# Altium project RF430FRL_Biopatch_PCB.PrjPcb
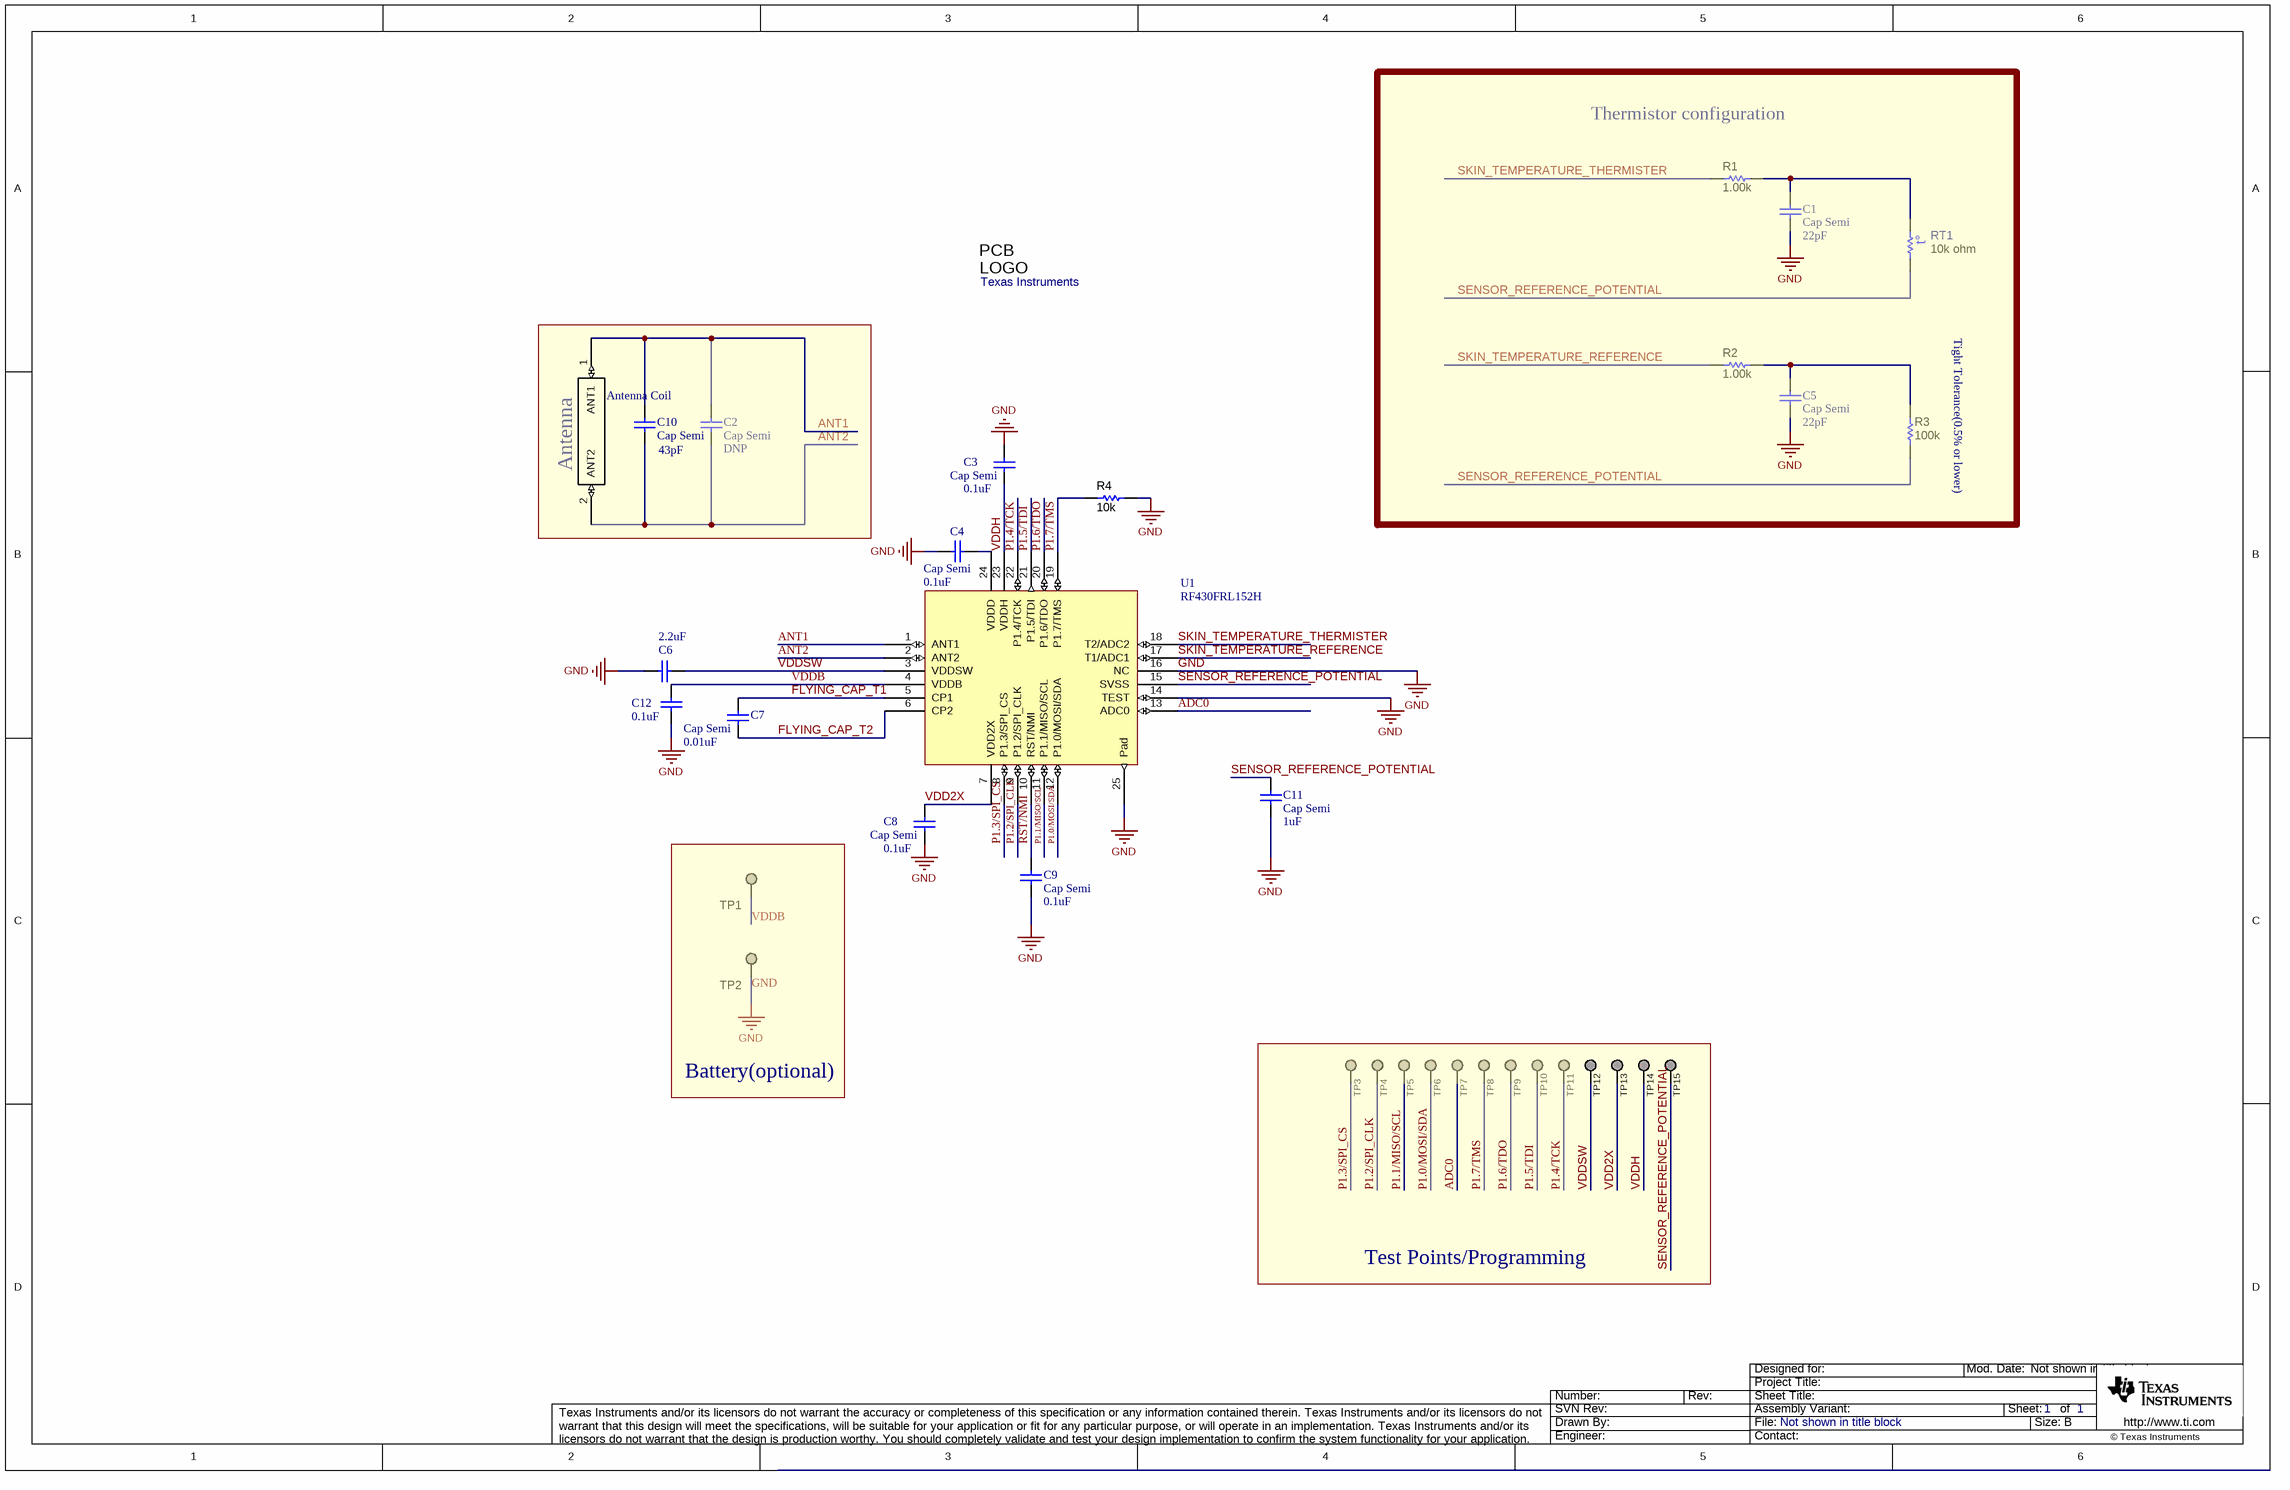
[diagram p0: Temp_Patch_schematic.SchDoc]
1 sheet, 35 parts. Net scope: global (net labels, ports and power ports of the same name join across sheets).
Board file: RF430FRL_Biopatch_Layout.PcbDoc

## Sheet Temp_Patch_schematic.SchDoc
size 431 x 279 mm; Date: Not shown in title block; ApprovedBy: Not shown in title block; CheckedBy: Not shown in title block; Author: Not shown in title block; CompanyName: Not shown in title block; Engineer: Not shown in title block; Organization: Not shown in title block; Address1: Not shown in title block; Address2: Not shown in title block; Address3: Not shown in title block; Address4: Not shown in title block; DocumentNumber: 1; Revision: Use project parameter SCH_Rev; SheetNumber: 1; SheetTotal: 1; PageSetup: Record=PageOptions|CenterHorizontal=True|CenterVertical=True|PrintScale=0.64|XCorrection=1.00|YCorrection=1.00|PrintKind=0|BorderSize=5000000|LeftOffset=0|BottomOffset=0|Orientation=2|PaperLength=1000|PaperWidth=1000|Scale=100|PaperSource=15|PrintQuality=600|MediaType=1|DitherType=10|PaperKind=Letter|PrintScaleMode=1

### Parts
Antenna_Coil  Antenna Coil  [PCBComponent_1]
C1  Cap Semi  value 22pF  [0402]
C2  Cap Semi  value DNP  [0402]
C3  Cap Semi  value 0.1uF  [0402]
C4  Cap Semi  value 0.1uF  [0402]
C5  Cap Semi  value 22pF  [0402]
C6  value 2.2uF  [0402]  (hidden comment: Cap Semi)
C7  Cap Semi  value 0.01uF  [0402]
C8  Cap Semi  value 0.1uF  [0402]
C9  Cap Semi  value 0.1uF  [0402]
C10  Cap Semi  value 43pF  [0402]
C11  Cap Semi  value 1uF  [0402]
C12  value 0.1uF  [0402]  (hidden comment: Cap Semi)
Logo?  Texas Instruments  [TI_Symbol_Overlay_Small]  (no BOM)
R1  ValueDisplayed: 1.00k  [0402]  (hidden comment: CRCW04021K00FKED)
R2  ValueDisplayed: 1.00k  [0402]  (hidden comment: CRCW04021K00FKED)
R3  ValueDisplayed: 100k  [0402]  (hidden comment: CRCW0402100KJNED)
R4  ValueDisplayed: 10k  [0402]  (hidden comment: CRCW040210K0JNED)
RT1  value 10k ohm  [0603]  (hidden comment: 103AT-2)
TP1  TESTPOINT  [TESTPOINT]  (value not drawn)  (no BOM)
TP2  TESTPOINT  [TESTPOINT]  (value not drawn)  (no BOM)
TP3  TESTPOINT  [TESTPOINT]  (value not drawn)  (no BOM)
TP4  TESTPOINT  [TESTPOINT]  (value not drawn)  (no BOM)
TP5  TESTPOINT  [TESTPOINT]  (value not drawn)  (no BOM)
TP6  TESTPOINT  [TESTPOINT]  (value not drawn)  (no BOM)
TP7  TESTPOINT  [TESTPOINT]  (value not drawn)  (no BOM)
TP8  TESTPOINT  [TESTPOINT]  (value not drawn)  (no BOM)
TP9  TESTPOINT  [TESTPOINT]  (value not drawn)  (no BOM)
TP10  TESTPOINT  [TESTPOINT]  (value not drawn)  (no BOM)
TP11  TESTPOINT  [TESTPOINT]  (value not drawn)  (no BOM)
TP12  TESTPOINT  [TESTPOINT]  (value not drawn)  (no BOM)
TP13  TESTPOINT  [TESTPOINT]  (value not drawn)  (no BOM)
TP14  TESTPOINT  [TESTPOINT]  (value not drawn)  (no BOM)
TP15  TESTPOINT  [TESTPOINT]  (value not drawn)  (no BOM)
U1  RF430FRL152H  [RGE24_2P7X2P7]

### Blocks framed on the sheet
Thermistor configuration: C1 C5 R1-R3 RT1
Antenna: Antenna_Coil C2 C10
Battery(optional): TP1 TP2
Test Points/Programming: TP3-TP15

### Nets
GND: C1.1 C3.2 C4.2 C5.1 C6.2 C8.1 C9.1 C11.1 C12.1 R4.2 TP2.1 U1.14(TEST) U1.16(NC) U1.25(Pad)
ADC0: TP7.1 U1.13(ADC0)
ANT1: Antenna_Coil.1(ANT1) C2.2 C10.2 U1.1(ANT1)
ANT2: Antenna_Coil.2(ANT2) C2.1 C10.1 U1.2(ANT2)
FLYING_CAP_T1: C7.2 U1.5(CP1)
FLYING_CAP_T2: C7.1 U1.6(CP2)
P1.0/MOSI/SDA: TP6.1 U1.12(P1.0/MOSI/SDA)
P1.1/MISO/SCL: TP5.1 U1.11(P1.1/MISO/SCL)
P1.2/SPI_CLK: TP4.1 U1.9(P1.2/SPI_CLK)
P1.3/SPI_CS: TP3.1 U1.8(P1.3/SPI_CS)
P1.4/TCK: TP11.1 U1.22(P1.4/TCK)
P1.5/TDI: TP10.1 U1.21(P1.5/TDI)
P1.6/TDO: TP9.1 U1.20(P1.6/TDO)
P1.7/TMS: R4.1 TP8.1 U1.19(P1.7/TMS)
RST/NMI: C9.2 U1.10(RST/NMI)
SENSOR_REFERENCE_POTENTIAL: C11.2 R3.1 RT1.1 TP15.1 U1.15(SVSS)
SKIN_TEMPERATURE_REFERENCE: R2.1 U1.17(T1/ADC1)
SKIN_TEMPERATURE_THERMISTER: R1.1 U1.18(T2/ADC2)
VDD2X: C8.2 TP13.1 U1.7(VDD2X)
VDDB: C12.2 TP1.1 U1.4(VDDB)
VDDH: C3.1 TP14.1 U1.23(VDDH)
VDDSW: C6.1 TP12.1 U1.3(VDDSW)
NetC1_2: C1.2 R1.2 RT1.2
NetC4_1: C4.1 U1.24(VDDD)
NetC5_2: C5.2 R2.2 R3.2

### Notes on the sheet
- (near R3) Tight Tolerance(0.5% or lower)

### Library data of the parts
Antenna_Coil = Component_1
C1-C12 = Cap Semi: Capacitor (Semiconductor SIM Model)
Logo? = TI_Logo: Texas Instrument Corporate Signature; SymbolCreator: a0412235
R1 R2 = CRCW04021K00FKED: RES, 1.00 k, 1%, 0.063 W, 0402; Manufacturer: Vishay-Dale; CompType: Resistor; Res_ohm: 1000; Value: 1.00k; Value_Code: 1k00; Tolerance_%: 1; Power_W: 0.063; Value2: 0.063W; VDC_V: 50; TempCo: 100 ppm/C; EIA_Code: E96; U/M: EA
R3 = CRCW0402100KJNED: RES, 100 k, 5%, 0.063 W, 0402; Manufacturer: Vishay-Dale; CompType: Resistor; Res_ohm: 100000; Value: 100k; Tolerance_%: 5; Power_W: 0.063; Value2: 0.063W; VDC_V: 50; TempCo: 200 ppm/C; EIA_Code: E24; U/M: EA
R4 = CRCW040210K0JNED: RES, 10 k, 5%, 0.063 W, 0402; Manufacturer: Vishay-Dale; CompType: Resistor; Res_ohm: 10000; Value: 10k; Value_Code: 10k0; Tolerance_%: 5; Power_W: 0.063; Value2: 0.063W; VDC_V: 50; TempCo: 200 ppm/C; EIA_Code: E24; U/M: EA
RT1 = 103AT-2: Thermistor NTC, 10.0k ohm, 1%, Disc, 5x8.4 mm; Manufacturer: SEMITEC Corporation; Tolerance_%: 1; Power_W: 0.01; TaMin_C: -50; TaMax_C: 110; U/M: EA
TP1-TP15 = TESTPOINT: TEST POINT.  No entry in BOM.
U1 = Sensor Transponder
